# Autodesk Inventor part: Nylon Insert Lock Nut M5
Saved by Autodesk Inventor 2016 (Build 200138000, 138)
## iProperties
Created: 2016-03
Part Number: Nylon Insert Lock Nut M5
Material: Generic
Document SubType Name: Modeling
Designer: bongo_000
Density: 1 g/cm^3
Appearance: Default
Author: bongo_000
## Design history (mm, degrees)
feature "CUT-EXTRUDE1"
body "Solid1"
